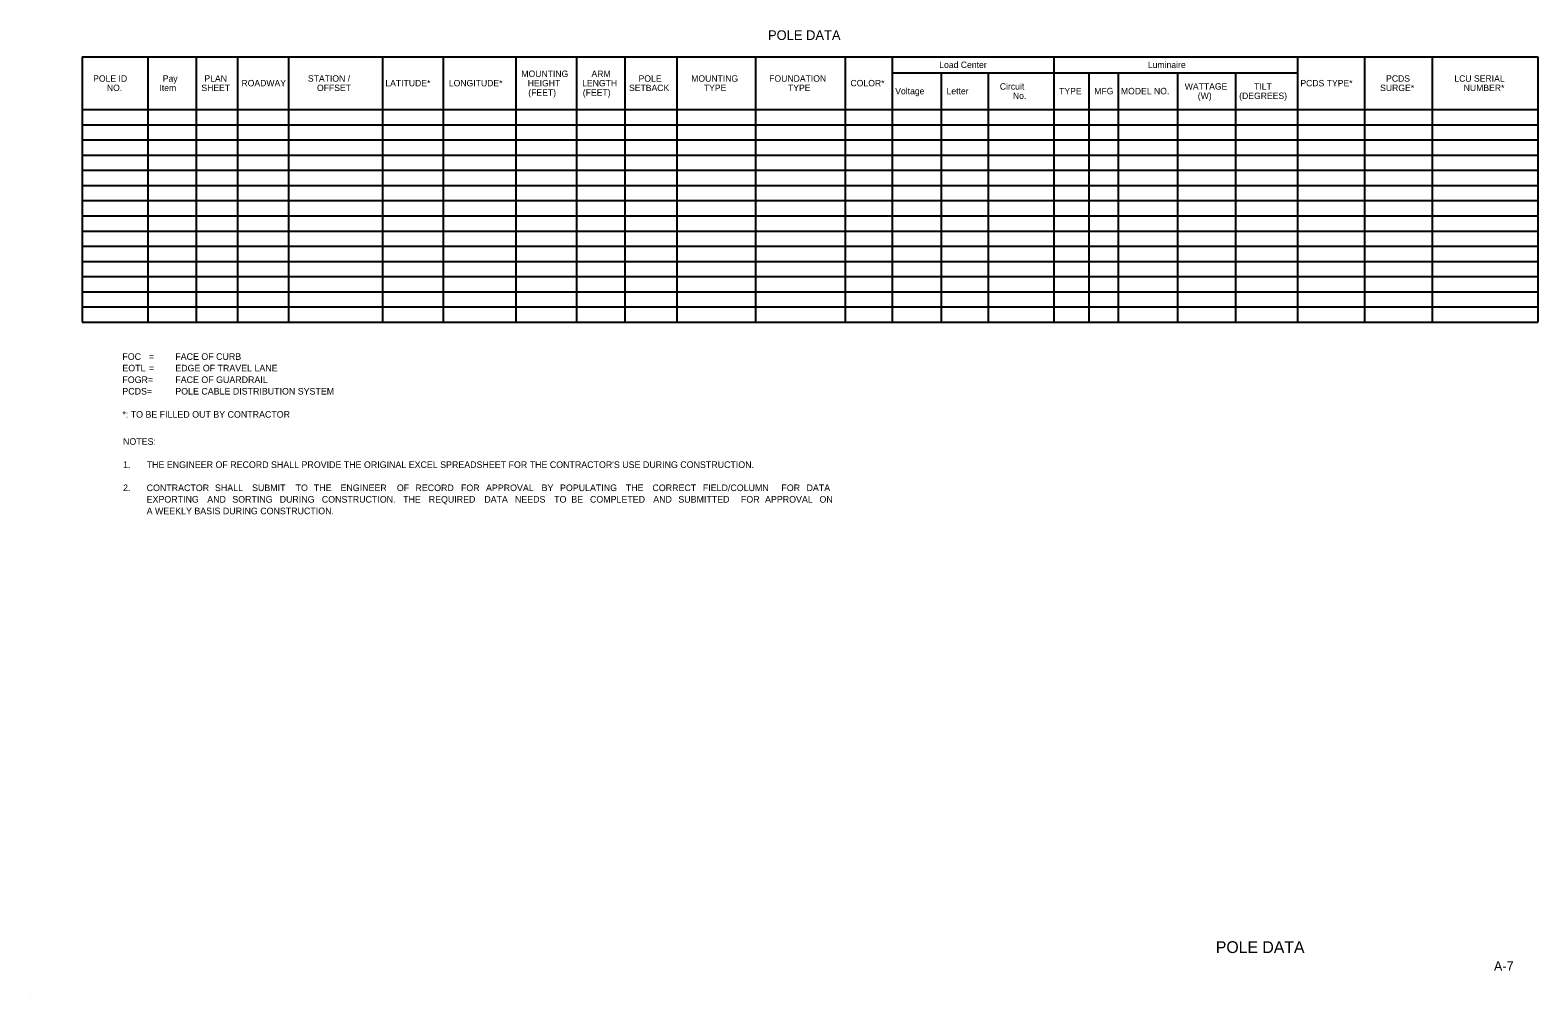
# Model space of a CAD drawing. Extents: x -830028.7 to -830012.7, y 1290283.4 to 1290293.6.
import ezdxf

# ---------------------------------------------------------------- set-up
doc = ezdxf.new("R2010")
doc.units = 0
for name, color, linetype in [('AdhocPoint_dp', 7, 'Continuous'), ('SumBoxBorder_dp', 7, 'Continuous'), ('SumBoxLines_dp', 7, 'Continuous'), ('SumBoxLinesMin_dp', 7, 'Continuous'), ('TextLabel', 7, 'Continuous'), ('TextMisc', 7, 'Continuous'), ('TextNotes', 7, 'Continuous'), ('TextShtNo', 7, 'Continuous')]:
    doc.layers.add(name, color=color, linetype=linetype)

msp = doc.modelspace()

# ---------------------------------------------------------------- linework, layer by layer
at = {"layer": 'AdhocPoint_dp'}
msp.add_line((-830028.694, 1290283.415), (-830028.694, 1290283.415), dxfattribs=at)
at = {"layer": 'SumBoxBorder_dp'}
for p, q in [((-830028.144, 1290293.343), (-830012.744, 1290293.343)), ((-830028.144, 1290293.343), (-830012.744, 1290293.343)), ((-830028.144, 1290293.343), (-830028.144, 1290290.536)), ((-830027.449, 1290293.343), (-830027.449, 1290292.786)), ((-830027.449, 1290293.343), (-830027.449, 1290292.786)), ((-830026.938, 1290293.343), (-830026.938, 1290292.786)), ((-830026.938, 1290293.343), (-830026.938, 1290292.786)), ((-830026.5, 1290293.343), (-830026.5, 1290292.786)), ((-830026.5, 1290293.343), (-830026.5, 1290292.786)), ((-830025.959, 1290293.343), (-830025.959, 1290292.786)), ((-830025.959, 1290293.343), (-830025.959, 1290292.786)), ((-830024.966, 1290293.343), (-830024.966, 1290292.786)), ((-830024.966, 1290293.343), (-830024.966, 1290292.786)), ((-830024.323, 1290293.343), (-830024.323, 1290292.786)), ((-830024.323, 1290293.343), (-830024.323, 1290292.786)), ((-830023.556, 1290293.343), (-830023.556, 1290292.786)), ((-830023.556, 1290293.343), (-830023.556, 1290292.786)), ((-830022.913, 1290293.343), (-830022.913, 1290292.786)), ((-830022.913, 1290293.343), (-830022.913, 1290292.786)), ((-830022.401, 1290293.343), (-830022.401, 1290292.786)), ((-830022.401, 1290293.343), (-830022.401, 1290292.786)), ((-830021.853, 1290293.343), (-830021.853, 1290292.786)), ((-830021.853, 1290293.343), (-830021.853, 1290292.786)), ((-830021.021, 1290293.343), (-830021.021, 1290292.786)), ((-830021.021, 1290293.343), (-830021.021, 1290292.786)), ((-830020.071, 1290293.343), (-830020.071, 1290292.786)), ((-830020.071, 1290293.343), (-830020.071, 1290292.786)), ((-830019.574, 1290293.343), (-830019.574, 1290292.786)), ((-830019.574, 1290293.343), (-830019.574, 1290292.786)), ((-830017.865, 1290293.343), (-830017.865, 1290292.786)), ((-830017.865, 1290293.343), (-830017.865, 1290292.786)), ((-830015.286, 1290293.343), (-830015.286, 1290292.786)), ((-830015.286, 1290293.343), (-830015.286, 1290292.786)), ((-830014.577, 1290293.343), (-830014.577, 1290292.786)), ((-830014.577, 1290293.343), (-830014.577, 1290292.786)), ((-830013.861, 1290293.343), (-830013.861, 1290292.786)), ((-830013.861, 1290293.343), (-830013.861, 1290292.786)), ((-830012.744, 1290293.343), (-830012.744, 1290290.536)), ((-830019.574, 1290293.175), (-830015.286, 1290293.175)), ((-830019.574, 1290293.175), (-830015.286, 1290293.175)), ((-830019.055, 1290293.175), (-830019.055, 1290292.786)), ((-830019.055, 1290293.175), (-830019.055, 1290292.786)), ((-830018.559, 1290293.175), (-830018.559, 1290292.786)), ((-830018.559, 1290293.175), (-830018.559, 1290292.786)), ((-830017.492, 1290293.175), (-830017.492, 1290292.786)), ((-830017.492, 1290293.175), (-830017.492, 1290292.786)), ((-830017.185, 1290293.175), (-830017.185, 1290292.786)), ((-830017.185, 1290293.175), (-830017.185, 1290292.786)), ((-830016.557, 1290293.175), (-830016.557, 1290292.786)), ((-830016.557, 1290293.175), (-830016.557, 1290292.786)), ((-830015.943, 1290293.175), (-830015.943, 1290292.786)), ((-830015.943, 1290293.175), (-830015.943, 1290292.786)), ((-830028.144, 1290292.786), (-830012.744, 1290292.786)), ((-830028.144, 1290292.786), (-830012.744, 1290292.786)), ((-830028.144, 1290290.536), (-830012.744, 1290290.536))]:
    msp.add_line(p, q, dxfattribs=at)
at = {"layer": 'SumBoxLines_dp'}
for p, q in [((-830027.449, 1290292.786), (-830027.449, 1290290.536)), ((-830027.449, 1290292.786), (-830027.449, 1290290.536)), ((-830026.938, 1290292.786), (-830026.938, 1290290.536)), ((-830026.938, 1290292.786), (-830026.938, 1290290.536)), ((-830026.5, 1290292.786), (-830026.5, 1290290.536)), ((-830026.5, 1290292.786), (-830026.5, 1290290.536)), ((-830025.959, 1290292.786), (-830025.959, 1290290.536)), ((-830025.959, 1290292.786), (-830025.959, 1290290.536)), ((-830024.966, 1290292.786), (-830024.966, 1290290.536)), ((-830024.966, 1290292.786), (-830024.966, 1290290.536)), ((-830024.323, 1290292.786), (-830024.323, 1290290.536)), ((-830024.323, 1290292.786), (-830024.323, 1290290.536)), ((-830023.556, 1290292.786), (-830023.556, 1290290.536)), ((-830023.556, 1290292.786), (-830023.556, 1290290.536)), ((-830022.913, 1290292.786), (-830022.913, 1290290.536)), ((-830022.913, 1290292.786), (-830022.913, 1290290.536)), ((-830022.401, 1290292.786), (-830022.401, 1290290.536)), ((-830022.401, 1290292.786), (-830022.401, 1290290.536)), ((-830021.853, 1290292.786), (-830021.853, 1290290.536)), ((-830021.853, 1290292.786), (-830021.853, 1290290.536)), ((-830021.021, 1290292.786), (-830021.021, 1290290.536)), ((-830021.021, 1290292.786), (-830021.021, 1290290.536)), ((-830020.071, 1290292.786), (-830020.071, 1290290.536)), ((-830020.071, 1290292.786), (-830020.071, 1290290.536)), ((-830019.574, 1290292.786), (-830019.574, 1290290.536)), ((-830019.574, 1290292.786), (-830019.574, 1290290.536)), ((-830019.055, 1290292.786), (-830019.055, 1290290.536)), ((-830019.055, 1290292.786), (-830019.055, 1290290.536)), ((-830018.559, 1290292.786), (-830018.559, 1290290.536)), ((-830018.559, 1290292.786), (-830018.559, 1290290.536)), ((-830017.865, 1290292.786), (-830017.865, 1290290.536)), ((-830017.865, 1290292.786), (-830017.865, 1290290.536)), ((-830017.492, 1290292.786), (-830017.492, 1290290.536)), ((-830017.492, 1290292.786), (-830017.492, 1290290.536)), ((-830017.185, 1290292.786), (-830017.185, 1290290.536)), ((-830017.185, 1290292.786), (-830017.185, 1290290.536)), ((-830016.557, 1290292.786), (-830016.557, 1290290.536)), ((-830016.557, 1290292.786), (-830016.557, 1290290.536)), ((-830015.943, 1290292.786), (-830015.943, 1290290.536)), ((-830015.943, 1290292.786), (-830015.943, 1290290.536)), ((-830015.286, 1290292.786), (-830015.286, 1290290.536)), ((-830015.286, 1290292.786), (-830015.286, 1290290.536)), ((-830014.577, 1290292.786), (-830014.577, 1290290.536)), ((-830013.861, 1290292.786), (-830013.861, 1290290.536))]:
    msp.add_line(p, q, dxfattribs=at)
at = {"layer": 'SumBoxLinesMin_dp'}
for p, q in [((-830028.144, 1290292.625), (-830012.744, 1290292.625)), ((-830028.144, 1290292.625), (-830012.744, 1290292.625)), ((-830028.144, 1290292.465), (-830012.744, 1290292.465)), ((-830028.144, 1290292.465), (-830012.744, 1290292.465)), ((-830028.144, 1290292.304), (-830012.744, 1290292.304)), ((-830028.144, 1290292.304), (-830012.744, 1290292.304)), ((-830028.144, 1290292.143), (-830012.744, 1290292.143)), ((-830028.144, 1290292.143), (-830012.744, 1290292.143)), ((-830028.144, 1290291.982), (-830012.744, 1290291.982)), ((-830028.144, 1290291.982), (-830012.744, 1290291.982)), ((-830028.144, 1290291.822), (-830012.744, 1290291.822)), ((-830028.144, 1290291.822), (-830012.744, 1290291.822)), ((-830028.144, 1290291.661), (-830012.744, 1290291.661)), ((-830028.144, 1290291.661), (-830012.744, 1290291.661)), ((-830028.144, 1290291.5), (-830012.744, 1290291.5)), ((-830028.144, 1290291.5), (-830012.744, 1290291.5)), ((-830028.144, 1290291.34), (-830012.744, 1290291.34)), ((-830028.144, 1290291.34), (-830012.744, 1290291.34)), ((-830028.144, 1290291.179), (-830012.744, 1290291.179)), ((-830028.144, 1290291.179), (-830012.744, 1290291.179)), ((-830028.144, 1290291.018), (-830012.744, 1290291.018)), ((-830028.144, 1290291.018), (-830012.744, 1290291.018)), ((-830028.144, 1290290.857), (-830012.744, 1290290.857)), ((-830028.144, 1290290.857), (-830012.744, 1290290.857)), ((-830028.144, 1290290.697), (-830012.744, 1290290.697)), ((-830028.144, 1290290.697), (-830012.744, 1290290.697))]:
    msp.add_line(p, q, dxfattribs=at)

# ---------------------------------------------------------------- texts
at = {"layer": 'TextLabel'}
for s, height, p in [('POLE DATA', 0.1023, (-830020.888, 1290293.522)), ('Load Center', 0.06818, (-830019.076, 1290293.225)), ('Luminaire', 0.0682, (-830016.869, 1290293.225)), ('POLE ID', 0.0682, (-830028.027, 1290293.08)), ('Pay', 0.0682, (-830027.291, 1290293.08)), ('PLAN', 0.0682, (-830026.85, 1290293.08)), ('STATION /', 0.0682, (-830025.755, 1290293.08)), ('MOUNTING', 0.0682, (-830023.497, 1290293.13)), ('ARM', 0.0682, (-830022.755, 1290293.13)), ('POLE', 0.0682, (-830022.257, 1290293.08)), ('MOUNTING', 0.0682, (-830021.7, 1290293.08)), ('FOUNDATION', 0.0682, (-830020.875, 1290293.08)), ('PCDS', 0.0682, (-830014.349, 1290293.08)), ('LCU SERIAL', 0.0682, (-830013.627, 1290293.08)), ('NO.', 0.0682, (-830027.882, 1290292.981)), ('Item', 0.0682, (-830027.326, 1290292.981)), ('SHEET', 0.0682, (-830026.882, 1290292.981)), ('ROADWAY', 0.0682, (-830026.458, 1290293.031)), ('OFFSET', 0.0682, (-830025.659, 1290292.981)), ('LATITUDE*', 0.0682, (-830024.936, 1290293.031)), ('LONGITUDE*', 0.0682, (-830024.264, 1290293.031)), ('HEIGHT', 0.0682, (-830023.43, 1290293.031)), ('(FEET)', 0.0682, (-830023.424, 1290292.931)), ('LENGTH', 0.0682, (-830022.854, 1290293.031)), ('(FEET)', 0.0682, (-830022.847, 1290292.931)), ('SETBACK', 0.0682, (-830022.358, 1290292.981)), ('TYPE', 0.0682, (-830021.567, 1290292.981)), ('TYPE', 0.0682, (-830020.676, 1290292.981)), ('COLOR*', 0.0682, (-830020.015, 1290293.031)), ('Voltage', 0.0682, (-830019.542, 1290292.947)), ('Letter', 0.0682, (-830018.999, 1290292.947)), ('Circuit', 0.0682, (-830018.435, 1290292.996)), ('No.', 0.0682, (-830018.297, 1290292.897)), ('TYPE', 0.0682, (-830017.808, 1290292.947)), ('MFG', 0.0682, (-830017.436, 1290292.947)), ('MODEL NO.', 0.0682, (-830017.154, 1290292.947)), ('WATTAGE', 0.0682, (-830016.479, 1290292.996)), ('(W)', 0.0682, (-830016.341, 1290292.897)), ('(DEGREES)', 0.0682, (-830015.903, 1290292.897)), ('TILT', 0.0682, (-830015.745, 1290292.996)), ('PCDS TYPE*', 0.0682, (-830015.256, 1290293.031)), ('SURGE*', 0.0682, (-830014.412, 1290292.981)), ('NUMBER*', 0.0682, (-830013.528, 1290292.981)), ('FOC', 0.07, (-830027.718, 1290290.136)), ('EOTL', 0.07, (-830027.718, 1290290.014)), ('=', 0.07, (-830027.438, 1290290.136)), ('FACE OF CURB', 0.07, (-830027.158, 1290290.136)), ('EDGE OF TRAVEL LANE', 0.07, (-830027.158, 1290290.014)), ('FOGR=', 0.07, (-830027.718, 1290289.891)), ('=', 0.07, (-830027.438, 1290290.014)), ('FACE OF GUARDRAIL', 0.07, (-830027.158, 1290289.891)), ('PCDS=', 0.07, (-830027.718, 1290289.769)), ('POLE CABLE DISTRIBUTION SYSTEM', 0.07, (-830027.158, 1290289.769)), ('*: TO BE FILLED OUT BY CONTRACTOR', 0.07, (-830027.718, 1290289.524))]:
    msp.add_text(s, height=height, dxfattribs=at).set_placement(p)
at = {"layer": 'TextMisc'}
msp.add_text('       POLE DATA       ', height=0.125, dxfattribs=at).set_placement((-830016.475, 1290283.858))
at = {"layer": 'TextNotes'}
for s, p in [('NOTES:', (-830027.711, 1290289.237)), ('1.', (-830027.711, 1290288.992)), ("THE ENGINEER OF RECORD SHALL PROVIDE THE ORIGINAL EXCEL SPREADSHEET FOR THE CONTRACTOR'S USE DURING CONSTRUCTION.", (-830027.461, 1290288.992)), ('2.', (-830027.711, 1290288.747)), ('CONTRACTOR ', (-830027.461, 1290288.747)), ('SHALL ', (-830026.738, 1290288.747)), ('SUBMIT ', (-830026.346, 1290288.747)), ('TO ', (-830025.885, 1290288.747)), ('THE ', (-830025.692, 1290288.747)), ('ENGINEER ', (-830025.41, 1290288.747)), ('OF ', (-830024.814, 1290288.747)), ('RECORD ', (-830024.617, 1290288.747)), ('FOR ', (-830024.136, 1290288.747)), ('APPROVAL ', (-830023.871, 1290288.747)), ('BY ', (-830023.283, 1290288.747)), ('POPULATING ', (-830023.088, 1290288.747)), ('THE ', (-830022.392, 1290288.747)), ('CORRECT ', (-830022.11, 1290288.747)), ('FIELD/COLUMN ', (-830021.577, 1290288.747)), ('FOR ', (-830020.746, 1290288.747)), ('DATA ', (-830020.48, 1290288.747)), ('EXPORTING ', (-830027.461, 1290288.625)), ('AND ', (-830026.82, 1290288.625)), ('SORTING ', (-830026.555, 1290288.625)), ('DURING ', (-830026.054, 1290288.625)), ('CONSTRUCTION. ', (-830025.608, 1290288.625)), ('THE ', (-830024.748, 1290288.625)), ('REQUIRED ', (-830024.477, 1290288.625)), ('DATA ', (-830023.889, 1290288.625)), ('NEEDS ', (-830023.565, 1290288.625)), ('TO ', (-830023.15, 1290288.625)), ('BE ', (-830022.968, 1290288.625)), ('COMPLETED ', (-830022.771, 1290288.625)), ('AND ', (-830022.102, 1290288.625)), ('SUBMITTED ', (-830021.836, 1290288.625)), ('FOR ', (-830021.174, 1290288.625)), ('APPROVAL ', (-830020.919, 1290288.625)), ('ON ', (-830020.343, 1290288.625)), ('A WEEKLY BASIS DURING CONSTRUCTION. ', (-830027.461, 1290288.502))]:
    msp.add_text(s, height=0.07, dxfattribs=at).set_placement(p)
at = {"layer": 'TextShtNo'}
msp.add_text('A-7', height=0.1, dxfattribs=at).set_placement((-830013.208, 1290283.67))

doc.saveas('drawing.dxf')
